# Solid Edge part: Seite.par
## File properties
Author: heha
Template: Normal.par
Last saved by: heha
Revision: 7
Application: Solid Edge
Dichte: 2,712 kg/dm^3
Genauigkeit: 0,990
Material: Aluminium, 1060
Teilflächenrmatvorlage: Aluminium
Füllformatvorlage: ANSI38(Aluminum)
Virtuelle Formatvorlage: Poliertes Aluminium
Coef. of Thermal Exp: 2.3e-05
Thermal Conductivity: 221.0
Specific Heat: 920.0
Modulus of Elasticity: 68947570000.0
Poission's Ratio: 0.33
Yield Stress: 27579028.0
Ultimate Stress: 68947570.0
Elongation: 0.0
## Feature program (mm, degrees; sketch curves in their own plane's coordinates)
sketch for "unnamed Protrusion 1" plane through (0, 0, 0) normal (0, -1, 0) x-axis (1, 0, 0)
  line (0, 0) -> (0, 0)
  line (-2, 28) -> (-10, 28)
  line (-10, 28) -> (-10, 26.7)
  line (-10, 26.7) -> (-6.9, 26.7)
  line (-6.9, 26.7) -> (-6.9, 25)
  line (-6.9, 25) -> (-10, 25)
  line (-10, 25) -> (-10, 22.4)
  line (-10, 22.4) -> (-9, 22.4)
  line (-9, 22.4) -> (-9, 23.6)
  line (-9, 23.6) -> (-7.4, 23.6)
  line (-7.4, 23.6) -> (-7.4, 22.4)
  line (-7.4, 22.4) -> (-6.3, 22.4)
  line (-6.3, 22.4) -> (-6.3, 23.5)
  line (-6.3, 23.5) -> (-5.3077, 23.5)
  arc centre (-4, 24) radius 1.4 from (-5.3077, 23.5) to (-4.5, 22.6923) cw
  line (-4.5, 21.2) -> (-4.5, 22.6923)
  line (-1.5, 21.2) -> (-4.5, 21.2)
  line (-1.5, 19.4) -> (-1.5, 21.2)
  line (-3.5, 19.4) -> (-1.5, 19.4)
  line (-3.5, 18.3) -> (-3.5, 19.4)
  line (-1.5, 18.3) -> (-3.5, 18.3)
  line (-1.5, 16.5) -> (-1.5, 18.3)
  line (-3.5, 16.5) -> (-1.5, 16.5)
  line (-3.5, 15.4) -> (-3.5, 16.5)
  line (-1.5, 15.4) -> (-3.5, 15.4)
  line (-1.5, 13.6) -> (-1.5, 15.4)
  line (-3.5, 13.6) -> (-1.5, 13.6)
  line (-3.5, 12.5) -> (-3.5, 13.6)
  line (-1.5, 12.5) -> (-3.5, 12.5)
  line (-1.5, 10.7) -> (-1.5, 12.5)
  line (-3.5, 10.7) -> (-1.5, 10.7)
  line (-3.5, 9.6) -> (-3.5, 10.7)
  line (-1.5, 9.6) -> (-3.5, 9.6)
  line (-1.5, 7.8) -> (-1.5, 9.6)
  line (-3.5, 7.8) -> (-1.5, 7.8)
  line (-3.5, 6.7) -> (-3.5, 7.8)
  line (-1.5, 6.7) -> (-3.5, 6.7)
  line (-1.5, 4.9) -> (-1.5, 6.7)
  line (-3.5, 4.9) -> (-1.5, 4.9)
  line (-3.5, 3.8) -> (-3.5, 4.9)
  line (-1.5, 3.8) -> (-3.5, 3.8)
  line (-1.5, 2) -> (-1.5, 3.8)
  line (-3.5, 2) -> (-1.5, 2)
  line (-3.5, 0.9) -> (-3.5, 2)
  line (-1.5, 0.9) -> (-3.5, 0.9)
  line (-1.5, 0) -> (-1.5, 0.9)
  line (-0.1, 0) -> (-1.5, 0)
  line (-0.1, 0.3) -> (-0.1, 0)
  line (0, 0.3) -> (-0.1, 0.3)
  line (0, 17.7) -> (0, 0.3)
  line (0, 17.7) -> (-0.1, 17.7)
  line (-0.1, 17.7) -> (-0.1, 18.3)
  line (-0.1, 18.3) -> (0, 18.3)
  line (0, 26) -> (0, 18.3)
  arc centre (-2, 26) radius 2 from (-2, 28) to (0, 26) cw
  dimension (linear) = 6.9
  dimension (linear) = 10
  dimension (linear) = 10
  dimension (linear) = 10
  dimension (linear) = 10
  dimension (linear) = 7.4
  dimension (linear) = 9
  dimension (linear) = 9
  dimension (linear) = 1.5
  dimension (linear) = 3.5
  dimension (linear) = 1.5
  dimension (linear) = 1.5
  dimension (linear) = 0.1
  dimension (linear) = 0.1
  dimension (linear) = 0.1
extrude "unnamed Protrusion 1" add finite 82 along -normal
fillet "R03" radius 0.3
mirror "unnamed Mirror 1" of "unnamed Protrusion 1", "R03" about plane through (0, 0, 0) normal (0, 0, 1)
extrude "unnamed Protrusion 2" add finite 82
fillet "unnamed Round 1"
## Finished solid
Body 1: solid body, 154 faces, 456 edges, 304 vertices.
  Faces by surface: plane 102, cylinder 52
  Edges by curve: line 352, circle 104
Bounding box of the edges (mm): 10.000 x 82.000 x 56.000, from (-10, 0, -28) to (0, 82, 28).
Cylindrical faces by radius (mm): R0.3 x48, R1.4 x2, R2 x2
Planar faces by outward normal: +x 11, +y 1, +z 25, -x 39, -y 1, -z 25
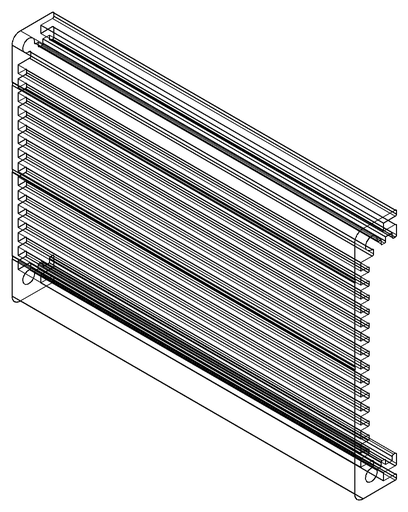
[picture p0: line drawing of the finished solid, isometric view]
